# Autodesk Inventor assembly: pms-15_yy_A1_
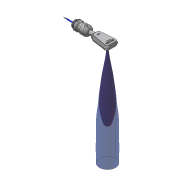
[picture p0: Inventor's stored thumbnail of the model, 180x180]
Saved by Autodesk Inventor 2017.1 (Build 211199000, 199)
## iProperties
Part Number: pms-15_yy_A1_
Material: Generisch
Document SubType Name: Assembly
Designer: Oliver Liedtke
Author: Oliver Liedtke
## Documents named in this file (6)
- J:\Projekte\Kunststoff-Blechteile\Zeichnungen\Bibliothek Inventor\3D Solids\pms\ipt_iam\pms-15_yy_A1_.iam
- J:\Projekte\Kunststoff-Blechteile\Zeichnungen\Bibliothek Inventor\Stecker_Kabel\Lapp\SKINTOP Hygienic-M20x1,5      Art_ Nr_ 531051209.ipt
- J:\Projekte\Kunststoff-Blechteile\Zeichnungen\Pommes-Sensor\Paddle V5\pms-xxx_yy_A1.ipt
- J:\Projekte\Kunststoff-Blechteile\Zeichnungen\Bibliothek Inventor\Stecker_Kabel\mic-Stecker\KSTG-M8.ipt
- J:\Projekte\Kunststoff-Blechteile\Zeichnungen\Bibliothek Inventor\3D Solids\Schallfelder\IPT\detection range 150 mm pipe + Blindzone.ipt
- J:\Projekte\Kunststoff-Blechteile\Zeichnungen\Bibliothek Inventor\3D Solids\Schallfelder\IPT\detection range 150 mm plate + Blindzone.ipt
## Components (5 placed, 5 different names)
1. pms-xxx_yy_A1:1 — Passend:1, Passend:2, Passend:3, Passend:4, Passend:5, Winkel:1, Passend:14, Passend:15, Passend:16, Passend:17
2. KSTG-M8:1 — Passend:2, Passend:3, Passend:4
3. SKINTOP Hygienic-M20x1,5      Art_ Nr_ 531051209:1 — Passend:1, Passend:5, Winkel:1
4. detection range 150 mm pipe + Blindzone:1 — Passend:16, Passend:17
5. detection range 150 mm plate + Blindzone:1 — Passend:14, Passend:15
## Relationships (10: Mate 9, Angle 1)
- Passend:1 [Mate]: pms-xxx_yy_A1:1 ↔ SKINTOP Hygienic-M20x1,5      Art_ Nr_ 531051209:1
- Passend:2 [Mate]: pms-xxx_yy_A1:1 ↔ KSTG-M8:1
- Passend:3 [Mate]: pms-xxx_yy_A1:1 ↔ KSTG-M8:1
- Passend:4 [Mate]: pms-xxx_yy_A1:1 ↔ KSTG-M8:1
- Passend:5 [Mate]: pms-xxx_yy_A1:1 ↔ SKINTOP Hygienic-M20x1,5      Art_ Nr_ 531051209:1
- Winkel:1 [Angle]: pms-xxx_yy_A1:1 ↔ SKINTOP Hygienic-M20x1,5      Art_ Nr_ 531051209:1
- Passend:14 [Mate]: pms-xxx_yy_A1:1 ↔ detection range 150 mm plate + Blindzone:1
- Passend:15 [Mate]: pms-xxx_yy_A1:1 ↔ detection range 150 mm plate + Blindzone:1
- Passend:16 [Mate]: pms-xxx_yy_A1:1 ↔ detection range 150 mm pipe + Blindzone:1
- Passend:17 [Mate]: pms-xxx_yy_A1:1 ↔ detection range 150 mm pipe + Blindzone:1
